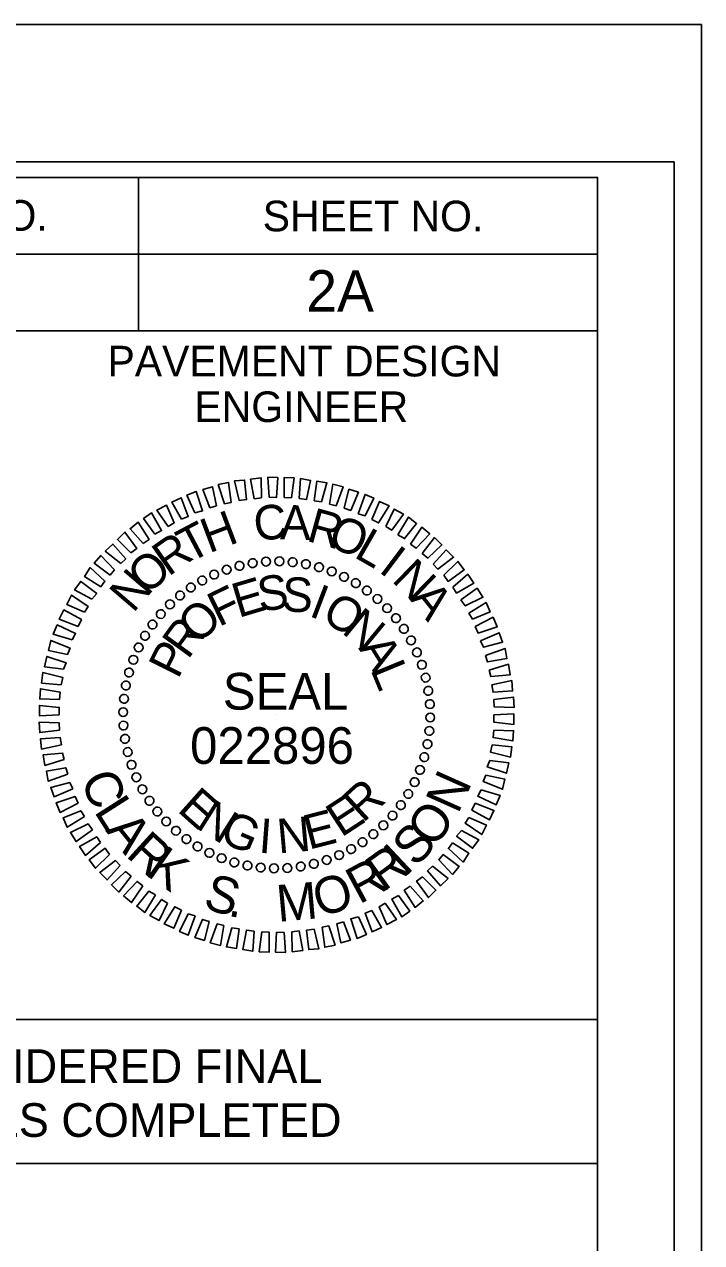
# Model space of a CAD drawing. Extents: x 575722 to 576066, y -53107 to -52774.
# Drawn here: x 575953.91 to 575964.97, y -52818.66 to -52798.76 of the extents above; entities that cross this region are included whole.
import ezdxf

# ---------------------------------------------------------------- set-up
doc = ezdxf.new("R2010")
doc.units = 0
for name, color, linetype in [('Sheet Cutting Line CELL', 7, 'Continuous'), ('Sheet Data Field CELL', 7, 'Continuous'), ('Sheet PE Seal Cell', 7, 'Continuous'), ('Sheet Plot Border Inside CELL', 7, 'Continuous'), ('Sheet Plot Border Outside CELL', 7, 'Continuous'), ('Sheet Sticker Exception Certification CELL', 7, 'Continuous'), ('Sheet Typical CELL', 7, 'Continuous')]:
    doc.layers.add(name, color=color, linetype=linetype)

# ---------------------------------------------------------------- blocks, each defined once
blk = doc.blocks.new('STICKER EXCEPTION CERTIFICATION')
at = {"layer": 'Sheet Sticker Exception Certification CELL'}
for p, q in [((0, -0.47), (0, 0)), ((0, 0), (4.0008, 0)), ((4.0008, -0.0003), (4.0008, -0.4703)), ((4.0008, -0.47), (0, -0.47))]:
    blk.add_line(p, q, dxfattribs=at)
for s, p in [('DOCUMENT NOT CONSIDERED FINAL', (0.4214, -0.2069)), ('UNLESS ALL SIGNATURES COMPLETED', (0.32, -0.3829))]:
    blk.add_text(s, height=0.11, dxfattribs=at).set_placement(p)

msp = doc.modelspace()

# ---------------------------------------------------------------- linework, layer by layer
at = {"layer": 'Sheet Cutting Line CELL'}
msp.add_line((575964.975, -52798.762), (575796.575, -52798.762), dxfattribs=at)
at = {"layer": 'Sheet PE Seal Cell'}
for p, q in [((575957.643, -52807.564), (575957.643, -52807.564)), ((575957.858, -52807.534), (575957.858, -52807.534)), ((575958.078, -52807.529), (575958.078, -52807.529)), ((575958.298, -52807.544), (575958.298, -52807.544)), ((575957.013, -52807.744), (575957.013, -52807.744)), ((575957.213, -52807.664), (575957.213, -52807.664)), ((575957.423, -52807.604), (575957.423, -52807.604)), ((575958.513, -52807.579), (575958.513, -52807.579)), ((575958.723, -52807.624), (575958.723, -52807.624)), ((575958.933, -52807.694), (575958.933, -52807.694)), ((575956.628, -52807.959), (575956.628, -52807.959)), ((575956.818, -52807.844), (575956.818, -52807.844)), ((575959.133, -52807.784), (575959.133, -52807.784)), ((575959.328, -52807.884), (575959.328, -52807.884)), ((575956.453, -52808.084), (575956.453, -52808.084)), ((575959.508, -52808.009), (575959.508, -52808.009)), ((575959.683, -52808.144), (575959.683, -52808.144)), ((575956.288, -52808.234), (575956.288, -52808.234)), ((575959.838, -52808.294), (575959.838, -52808.294)), ((575956.003, -52808.564), (575956.003, -52808.564)), ((575956.138, -52808.389), (575956.138, -52808.389)), ((575959.988, -52808.459), (575959.988, -52808.459)), ((575955.878, -52808.744), (575955.878, -52808.744)), ((575960.113, -52808.634), (575960.113, -52808.634)), ((575955.778, -52808.939), (575955.778, -52808.939)), ((575960.228, -52808.824), (575960.228, -52808.824)), ((575955.688, -52809.139), (575955.688, -52809.139)), ((575960.328, -52809.019), (575960.328, -52809.019)), ((575955.618, -52809.349), (575955.618, -52809.349)), ((575960.408, -52809.219), (575960.408, -52809.219)), ((575955.573, -52809.559), (575955.573, -52809.559)), ((575960.468, -52809.429), (575960.468, -52809.429)), ((575960.508, -52809.649), (575960.508, -52809.649)), ((575955.538, -52809.774), (575955.538, -52809.774)), ((575960.538, -52809.864), (575960.538, -52809.864)), ((575955.523, -52809.994), (575955.523, -52809.994)), ((575958.033, -52810.039), (575958.033, -52810.039)), ((575960.543, -52810.084), (575960.543, -52810.084)), ((575955.528, -52810.214), (575955.528, -52810.214)), ((575960.528, -52810.304), (575960.528, -52810.304)), ((575955.558, -52810.429), (575955.558, -52810.429)), ((575960.493, -52810.519), (575960.493, -52810.519)), ((575955.598, -52810.649), (575955.598, -52810.649)), ((575960.448, -52810.729), (575960.448, -52810.729)), ((575955.658, -52810.859), (575955.658, -52810.859)), ((575960.378, -52810.939), (575960.378, -52810.939)), ((575955.738, -52811.059), (575955.738, -52811.059)), ((575960.288, -52811.139), (575960.288, -52811.139)), ((575955.838, -52811.254), (575955.838, -52811.254)), ((575960.188, -52811.334), (575960.188, -52811.334)), ((575955.953, -52811.444), (575955.953, -52811.444)), ((575960.063, -52811.514), (575960.063, -52811.514)), ((575956.078, -52811.619), (575956.078, -52811.619)), ((575959.928, -52811.689), (575959.928, -52811.689)), ((575956.228, -52811.784), (575956.228, -52811.784)), ((575956.383, -52811.934), (575956.383, -52811.934)), ((575959.778, -52811.844), (575959.778, -52811.844)), ((575956.558, -52812.069), (575956.558, -52812.069)), ((575959.438, -52812.119), (575959.438, -52812.119)), ((575959.613, -52811.994), (575959.613, -52811.994)), ((575956.738, -52812.194), (575956.738, -52812.194)), ((575956.933, -52812.294), (575956.933, -52812.294)), ((575959.053, -52812.334), (575959.053, -52812.334)), ((575959.248, -52812.234), (575959.248, -52812.234)), ((575957.133, -52812.384), (575957.133, -52812.384)), ((575957.343, -52812.454), (575957.343, -52812.454)), ((575957.553, -52812.499), (575957.553, -52812.499)), ((575957.768, -52812.534), (575957.768, -52812.534)), ((575957.988, -52812.549), (575957.988, -52812.549)), ((575958.208, -52812.544), (575958.208, -52812.544)), ((575958.423, -52812.514), (575958.423, -52812.514)), ((575958.643, -52812.474), (575958.643, -52812.474)), ((575958.853, -52812.414), (575958.853, -52812.414))]:
    msp.add_line(p, q, dxfattribs=at)
for points in [[(575957.663, -52806.509), (575957.608, -52806.189), (575957.778, -52806.169), (575957.783, -52806.494)], [(575957.913, -52806.484), (575957.888, -52806.159), (575958.053, -52806.164), (575958.033, -52806.489)], [(575958.153, -52806.489), (575958.153, -52806.164), (575958.318, -52806.169), (575958.273, -52806.494)], [(575958.403, -52806.504), (575958.423, -52806.179), (575958.588, -52806.209), (575958.523, -52806.524)], [(575956.943, -52806.659), (575956.828, -52806.359), (575956.983, -52806.314), (575957.048, -52806.624)], [(575957.183, -52806.594), (575957.078, -52806.279), (575957.248, -52806.244), (575957.288, -52806.569)], [(575957.423, -52806.539), (575957.343, -52806.219), (575957.508, -52806.204), (575957.543, -52806.524)], [(575958.643, -52806.544), (575958.688, -52806.224), (575958.853, -52806.249), (575958.763, -52806.559)], [(575958.898, -52806.599), (575958.948, -52806.274), (575959.118, -52806.314), (575959.003, -52806.624)], [(575959.138, -52806.664), (575959.213, -52806.354), (575959.368, -52806.404), (575959.243, -52806.699)], [(575956.478, -52806.844), (575956.318, -52806.564), (575956.473, -52806.494), (575956.588, -52806.799)], [(575956.698, -52806.739), (575956.568, -52806.449), (575956.718, -52806.389), (575956.823, -52806.709)], [(575959.363, -52806.754), (575959.478, -52806.439), (575959.618, -52806.499), (575959.478, -52806.789)], [(575959.588, -52806.849), (575959.713, -52806.554), (575959.868, -52806.624), (575959.698, -52806.904)], [(575956.043, -52807.089), (575955.858, -52806.834), (575955.988, -52806.739), (575956.153, -52807.029)], [(575956.263, -52806.964), (575956.078, -52806.694), (575956.233, -52806.614), (575956.358, -52806.904)], [(575959.818, -52806.964), (575959.953, -52806.679), (575960.103, -52806.764), (575959.913, -52807.024)], [(575955.853, -52807.239), (575955.638, -52806.999), (575955.773, -52806.894), (575955.948, -52807.174)], [(575960.013, -52807.099), (575960.188, -52806.809), (575960.318, -52806.914), (575960.123, -52807.159)], [(575960.218, -52807.249), (575960.403, -52806.974), (575960.533, -52807.084), (575960.313, -52807.319)], [(575955.653, -52807.394), (575955.433, -52807.174), (575955.553, -52807.054), (575955.748, -52807.324)], [(575960.408, -52807.404), (575960.613, -52807.144), (575960.733, -52807.264), (575960.503, -52807.479)], [(575955.488, -52807.569), (575955.233, -52807.364), (575955.358, -52807.249), (575955.568, -52807.489)], [(575960.588, -52807.579), (575960.803, -52807.344), (575960.923, -52807.464), (575960.663, -52807.659)], [(575955.313, -52807.759), (575955.053, -52807.564), (575955.163, -52807.434), (575955.383, -52807.669)], [(575960.763, -52807.759), (575960.993, -52807.534), (575961.098, -52807.669), (575960.833, -52807.859)], [(575955.163, -52807.949), (575954.893, -52807.779), (575954.988, -52807.634), (575955.228, -52807.854)], [(575960.913, -52807.954), (575961.158, -52807.744), (575961.253, -52807.889), (575960.973, -52808.049)], [(575955.013, -52808.149), (575954.733, -52807.999), (575954.833, -52807.859), (575955.093, -52808.059)], [(575961.043, -52808.159), (575961.308, -52807.969), (575961.403, -52808.119), (575961.113, -52808.259)], [(575954.893, -52808.364), (575954.608, -52808.239), (575954.683, -52808.084), (575954.953, -52808.269)], [(575954.793, -52808.594), (575954.483, -52808.479), (575954.558, -52808.324), (575954.843, -52808.484)], [(575961.173, -52808.379), (575961.453, -52808.204), (575961.518, -52808.359), (575961.233, -52808.474)], [(575954.693, -52808.814), (575954.383, -52808.724), (575954.448, -52808.569), (575954.748, -52808.709)], [(575961.273, -52808.594), (575961.568, -52808.444), (575961.633, -52808.604), (575961.323, -52808.704)], [(575961.363, -52808.829), (575961.668, -52808.699), (575961.723, -52808.854), (575961.413, -52808.934)], [(575954.618, -52809.054), (575954.308, -52808.989), (575954.343, -52808.824), (575954.658, -52808.949)], [(575961.443, -52809.069), (575961.763, -52808.954), (575961.793, -52809.119), (575961.478, -52809.174)], [(575954.553, -52809.294), (575954.243, -52809.254), (575954.278, -52809.084), (575954.593, -52809.189)], [(575954.513, -52809.549), (575954.193, -52809.519), (575954.213, -52809.349), (575954.538, -52809.429)], [(575961.503, -52809.309), (575961.818, -52809.214), (575961.848, -52809.384), (575961.533, -52809.414)], [(575961.548, -52809.549), (575961.873, -52809.479), (575961.888, -52809.649), (575961.568, -52809.669)], [(575954.488, -52809.789), (575954.163, -52809.779), (575954.173, -52809.614), (575954.498, -52809.669)], [(575961.578, -52809.789), (575961.903, -52809.749), (575961.913, -52809.919), (575961.588, -52809.909)], [(575954.483, -52810.039), (575954.158, -52810.054), (575954.158, -52809.884), (575954.483, -52809.919)], [(575954.488, -52810.289), (575954.163, -52810.329), (575954.153, -52810.159), (575954.478, -52810.169)], [(575961.583, -52810.039), (575961.908, -52810.024), (575961.908, -52810.194), (575961.583, -52810.159)], [(575961.578, -52810.289), (575961.903, -52810.299), (575961.893, -52810.464), (575961.568, -52810.409)], [(575954.518, -52810.529), (575954.193, -52810.599), (575954.178, -52810.429), (575954.498, -52810.409)], [(575961.553, -52810.529), (575961.873, -52810.559), (575961.853, -52810.729), (575961.528, -52810.649)], [(575954.563, -52810.769), (575954.248, -52810.864), (575954.218, -52810.694), (575954.533, -52810.664)], [(575954.623, -52811.009), (575954.303, -52811.124), (575954.273, -52810.959), (575954.588, -52810.904)], [(575961.513, -52810.784), (575961.823, -52810.824), (575961.788, -52810.994), (575961.473, -52810.889)], [(575954.703, -52811.249), (575954.398, -52811.379), (575954.343, -52811.224), (575954.653, -52811.144)], [(575961.448, -52811.024), (575961.758, -52811.089), (575961.723, -52811.254), (575961.408, -52811.129)], [(575961.373, -52811.264), (575961.683, -52811.354), (575961.618, -52811.509), (575961.318, -52811.369)], [(575954.793, -52811.484), (575954.498, -52811.634), (575954.433, -52811.474), (575954.743, -52811.374)], [(575961.273, -52811.484), (575961.583, -52811.599), (575961.508, -52811.754), (575961.223, -52811.594)], [(575954.893, -52811.699), (575954.613, -52811.874), (575954.548, -52811.719), (575954.833, -52811.604)], [(575961.173, -52811.714), (575961.458, -52811.839), (575961.383, -52811.994), (575961.113, -52811.809)], [(575955.023, -52811.919), (575954.758, -52812.109), (575954.663, -52811.959), (575954.953, -52811.819)], [(575961.053, -52811.929), (575961.333, -52812.079), (575961.233, -52812.219), (575960.973, -52812.019)], [(575955.153, -52812.124), (575954.908, -52812.334), (575954.813, -52812.189), (575955.093, -52812.029)], [(575960.903, -52812.129), (575961.173, -52812.299), (575961.078, -52812.444), (575960.838, -52812.224)], [(575955.303, -52812.319), (575955.073, -52812.544), (575954.968, -52812.409), (575955.233, -52812.219)], [(575960.753, -52812.319), (575961.013, -52812.514), (575960.903, -52812.644), (575960.683, -52812.409)], [(575955.478, -52812.499), (575955.263, -52812.734), (575955.143, -52812.614), (575955.403, -52812.419)], [(575960.578, -52812.509), (575960.833, -52812.714), (575960.708, -52812.829), (575960.498, -52812.589)], [(575955.658, -52812.674), (575955.453, -52812.934), (575955.333, -52812.814), (575955.563, -52812.599)], [(575960.413, -52812.684), (575960.633, -52812.904), (575960.513, -52813.024), (575960.318, -52812.754)], [(575955.848, -52812.829), (575955.663, -52813.104), (575955.533, -52812.994), (575955.753, -52812.759)], [(575956.053, -52812.979), (575955.878, -52813.269), (575955.748, -52813.164), (575955.943, -52812.919)], [(575960.213, -52812.839), (575960.428, -52813.079), (575960.293, -52813.184), (575960.118, -52812.904)], [(575956.248, -52813.114), (575956.113, -52813.399), (575955.963, -52813.314), (575956.153, -52813.054)], [(575959.803, -52813.114), (575959.988, -52813.384), (575959.833, -52813.464), (575959.708, -52813.174)], [(575960.023, -52812.989), (575960.208, -52813.244), (575960.078, -52813.339), (575959.913, -52813.049)], [(575956.478, -52813.229), (575956.353, -52813.524), (575956.198, -52813.454), (575956.368, -52813.174)], [(575956.703, -52813.324), (575956.588, -52813.639), (575956.448, -52813.579), (575956.588, -52813.289)], [(575959.368, -52813.339), (575959.498, -52813.629), (575959.348, -52813.689), (575959.243, -52813.369)], [(575959.588, -52813.234), (575959.748, -52813.514), (575959.593, -52813.584), (575959.478, -52813.279)], [(575956.928, -52813.414), (575956.853, -52813.724), (575956.698, -52813.674), (575956.823, -52813.379)], [(575957.168, -52813.479), (575957.118, -52813.804), (575956.948, -52813.764), (575957.063, -52813.454)], [(575957.423, -52813.534), (575957.378, -52813.854), (575957.213, -52813.829), (575957.303, -52813.519)], [(575958.643, -52813.539), (575958.723, -52813.859), (575958.558, -52813.874), (575958.523, -52813.554)], [(575958.883, -52813.484), (575958.988, -52813.799), (575958.818, -52813.834), (575958.778, -52813.509)], [(575959.123, -52813.419), (575959.238, -52813.719), (575959.083, -52813.764), (575959.018, -52813.454)], [(575957.663, -52813.574), (575957.643, -52813.899), (575957.478, -52813.869), (575957.543, -52813.554)], [(575957.913, -52813.589), (575957.913, -52813.914), (575957.748, -52813.909), (575957.793, -52813.584)], [(575958.153, -52813.594), (575958.178, -52813.919), (575958.013, -52813.914), (575958.033, -52813.589)], [(575958.403, -52813.569), (575958.458, -52813.889), (575958.288, -52813.909), (575958.283, -52813.584)]]:
    msp.add_lwpolyline(points, close=True, dxfattribs=at)
for centre, major_axis in [((575957.426, -52807.605), (-0.0174, 0.0699)), ((575957.641, -52807.562), (-0.0113, 0.0711)), ((575957.858, -52807.537), (-0.005, 0.0718)), ((575958.077, -52807.531), (0.0013, 0.072)), ((575958.295, -52807.545), (0.0075, 0.0716)), ((575958.512, -52807.577), (0.0137, 0.0707)), ((575958.725, -52807.628), (0.0198, 0.0692)), ((575956.817, -52807.845), (-0.0349, 0.063)), ((575957.013, -52807.748), (-0.0293, 0.0658)), ((575957.217, -52807.668), (-0.0234, 0.0681)), ((575958.932, -52807.697), (0.0258, 0.0672)), ((575959.133, -52807.785), (0.0316, 0.0647)), ((575956.631, -52807.96), (-0.0403, 0.0597)), ((575959.325, -52807.889), (0.0371, 0.0617)), ((575959.507, -52808.01), (0.0423, 0.0582)), ((575956.291, -52808.235), (-0.05, 0.0518)), ((575956.455, -52808.09), (-0.0453, 0.056)), ((575959.679, -52808.146), (0.0472, 0.0543)), ((575956.14, -52808.393), (-0.0543, 0.0472)), ((575959.837, -52808.297), (0.0518, 0.05)), ((575956.004, -52808.565), (-0.0582, 0.0423)), ((575959.982, -52808.461), (0.056, 0.0453)), ((575960.112, -52808.636), (0.0597, 0.0403)), ((575955.883, -52808.747), (-0.0617, 0.0371)), ((575960.227, -52808.823), (0.063, 0.0349)), ((575955.779, -52808.939), (-0.0647, 0.0316)), ((575960.324, -52809.019), (0.0658, 0.0293)), ((575955.692, -52809.14), (-0.0672, 0.0258)), ((575960.405, -52809.222), (0.0681, 0.0234)), ((575955.622, -52809.348), (-0.0692, 0.0198)), ((575960.467, -52809.432), (0.0699, 0.0174)), ((575955.571, -52809.56), (-0.0707, 0.0137)), ((575955.539, -52809.777), (-0.0716, 0.0075)), ((575960.51, -52809.647), (0.0711, 0.0113)), ((575955.526, -52809.995), (-0.072, 0.0013)), ((575960.535, -52809.864), (0.0718, 0.005)), ((575955.531, -52810.214), (-0.0718, -0.005)), ((575960.541, -52810.083), (0.072, -0.0013)), ((575955.556, -52810.431), (-0.0711, -0.0113)), ((575960.527, -52810.301), (0.0716, -0.0075)), ((575960.495, -52810.517), (0.0707, -0.0137)), ((575955.6, -52810.646), (-0.0699, -0.0174)), ((575960.444, -52810.73), (0.0692, -0.0198)), ((575955.662, -52810.855), (-0.0681, -0.0234)), ((575960.375, -52810.938), (0.0672, -0.0258)), ((575955.742, -52811.059), (-0.0658, -0.0293)), ((575960.287, -52811.138), (0.0647, -0.0316)), ((575955.84, -52811.255), (-0.063, -0.0349)), ((575960.183, -52811.331), (0.0617, -0.0371)), ((575955.954, -52811.441), (-0.0597, -0.0403)), ((575956.084, -52811.617), (-0.056, -0.0453)), ((575960.062, -52811.513), (0.0582, -0.0423)), ((575956.229, -52811.781), (-0.0518, -0.05)), ((575959.926, -52811.684), (0.0543, -0.0472)), ((575956.388, -52811.932), (-0.0472, -0.0543)), ((575959.612, -52811.988), (0.0453, -0.056)), ((575959.775, -52811.843), (0.05, -0.0518)), ((575956.559, -52812.068), (-0.0423, -0.0582)), ((575956.741, -52812.189), (-0.0371, -0.0617)), ((575959.249, -52812.232), (0.0349, -0.063)), ((575959.436, -52812.118), (0.0403, -0.0597)), ((575956.934, -52812.293), (-0.0316, -0.0647)), ((575957.134, -52812.38), (-0.0258, -0.0672)), ((575958.85, -52812.41), (0.0234, -0.0681)), ((575959.053, -52812.33), (0.0293, -0.0658)), ((575957.342, -52812.45), (-0.0198, -0.0692)), ((575957.555, -52812.501), (-0.0137, -0.0707)), ((575957.771, -52812.533), (-0.0075, -0.0716)), ((575957.989, -52812.546), (-0.0013, -0.072)), ((575958.208, -52812.541), (0.005, -0.0718)), ((575958.426, -52812.516), (0.0113, -0.0711)), ((575958.64, -52812.472), (0.0174, -0.0699))]:
    msp.add_ellipse(centre, major_axis=major_axis, ratio=0.999708, dxfattribs=at)
at = {"layer": 'Sheet Plot Border Inside CELL'}
msp.add_lwpolyline([(575964.525, -52801.007), (575797.875, -52801.007), (575797.875, -52906.517), (575964.525, -52906.517)], close=True, dxfattribs=at)
at = {"layer": 'Sheet Plot Border Outside CELL'}
msp.add_lwpolyline([(575964.975, -52798.762), (575796.575, -52798.762), (575796.575, -52908.762), (575964.975, -52908.762)], close=True, dxfattribs=at)
at = {"layer": 'Sheet Typical CELL'}
for p, q in [((575955.775, -52801.267), (575955.775, -52803.767)), ((575943.27, -52802.517), (575963.275, -52802.517))]:
    msp.add_line(p, q, dxfattribs=at)
for points in [[(575963.275, -52801.262), (575813.275, -52801.262), (575813.275, -52906.262), (575963.275, -52906.262)], [(575943.27, -52801.262), (575963.275, -52801.262), (575963.275, -52803.767), (575943.27, -52803.767)], [(575953.275, -52803.767), (575963.275, -52803.767), (575963.275, -52815.017), (575953.275, -52815.017)]]:
    msp.add_lwpolyline(points, close=True, dxfattribs=at)

# ---------------------------------------------------------------- block references
at = {"layer": 'Sheet Sticker Exception Certification CELL', "xscale": 5, "yscale": 4.999999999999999}
msp.add_blockref('STICKER EXCEPTION CERTIFICATION', (575943.27, -52815.017), dxfattribs=at)

# ---------------------------------------------------------------- texts
at = {"layer": 'Sheet Data Field CELL'}
msp.add_text('2A ', height=0.675, dxfattribs=at).set_placement((575958.517, -52803.452))
at = {"layer": 'Sheet PE Seal Cell'}
for s, height, rotation, p in [('H', 0.564, 20.6195, (575956.928, -52807.404)), ('C', 0.564, 6.2199, (575957.688, -52807.204)), ('A', 0.564, 359.0203, (575958.083, -52807.174)), ('R', 0.564, 344.6211, (575958.503, -52807.194)), ('T', 0.564, 27.8198, (575956.603, -52807.569)), ('O', 0.564, 337.4212, (575958.838, -52807.269)), ('R', 0.564, 35.0205, (575956.263, -52807.789)), ('L', 0.564, 330.2209, (575959.278, -52807.454)), ('I', 0.564, 323.0201, (575959.683, -52807.694)), ('O', 0.564, 42.2217, (575955.918, -52808.099)), ('N', 0.564, 315.8189, (575959.898, -52807.849)), ('N', 0.564, 49.4235, (575955.688, -52808.389)), ('S', 0.564, 7.2556, (575957.753, -52808.354)), ('F', 0.564, 25.967, (575957.088, -52808.609)), ('E', 0.564, 16.6111, (575957.408, -52808.459)), ('S', 0.564, 357.9004, (575958.113, -52808.349)), ('I', 0.564, 339.1896, (575958.543, -52808.419)), ('A', 0.564, 308.6172, (575960.193, -52808.144)), ('O', 0.564, 329.8335, (575958.743, -52808.489)), ('O', 0.564, 44.6812, (575956.758, -52808.904)), ('N', 0.564, 320.4766, (575959.078, -52808.689)), ('R', 0.564, 54.0397, (575956.583, -52809.149)), ('P', 0.564, 63.3989, (575956.423, -52809.469)), ('A', 0.564, 301.7603, (575959.363, -52808.949)), ('L', 0.564, 292.4008, (575959.558, -52809.294)), ('SEAL', 0.5998, 360, (575957.153, -52809.954)), ('C', 0.6, 292.9481, (575954.82, -52811.093)), ('N', 0.6, 65.9082, (575960.995, -52811.672)), ('R', 0.564, 42.4814, (575959.443, -52811.814)), ('L', 0.6, 302.5303, (575955.04, -52811.614)), ('E', 0.564, 318.2769, (575956.393, -52811.604)), ('E', 0.564, 33.1241, (575959.088, -52812.049)), ('N', 0.564, 327.634, (575956.693, -52811.874)), ('O', 0.6, 54.3478, (575960.607, -52812.232)), ('A', 0.6, 308.805, (575955.23, -52811.931)), ('G', 0.564, 336.9902, (575957.073, -52812.099)), ('I', 0.564, 355.7012, (575957.728, -52812.289)), ('N', 0.564, 5.0564, (575958.063, -52812.304)), ('E', 0.564, 14.4118, (575958.558, -52812.244)), ('R', 0.6, 317.6453, (575955.554, -52812.339)), ('S', 0.6, 47.0221, (575960.307, -52812.542)), ('I', 0.6, 43.2201, (575960.136, -52812.688)), ('K', 0.6, 325.1256, (575955.875, -52812.643)), ('R', 0.6, 35.7399, (575959.773, -52812.939)), ('R', 0.6, 28.2596, (575959.381, -52813.141)), ('S', 0.6, 343.6099, (575956.812, -52813.192)), ('O', 0.6, 16.6992, (575958.732, -52813.348)), ('M', 0.6, 5.1697, (575958.056, -52813.421)), ('.', 0.6, 350.9356, (575957.224, -52813.322))]:
    msp.add_text(s, height=height, rotation=rotation, dxfattribs=at).set_placement(p)
msp.add_text('022896', height=0.5998, dxfattribs=at).set_placement((575956.619, -52810.84))
at = {"layer": 'Sheet Typical CELL'}
for s, height, p in [('PROJECT REFERENCE NO.', 0.50001, (575945.49, -52802.132)), ('SHEET NO.', 0.5, (575957.805, -52802.142)), ('PAVEMENT DESIGN', 0.50001, (575955.27, -52804.512)), ('ENGINEER', 0.5, (575956.69, -52805.257))]:
    msp.add_text(s, height=height, dxfattribs=at).set_placement(p)

doc.saveas('drawing.dxf')
